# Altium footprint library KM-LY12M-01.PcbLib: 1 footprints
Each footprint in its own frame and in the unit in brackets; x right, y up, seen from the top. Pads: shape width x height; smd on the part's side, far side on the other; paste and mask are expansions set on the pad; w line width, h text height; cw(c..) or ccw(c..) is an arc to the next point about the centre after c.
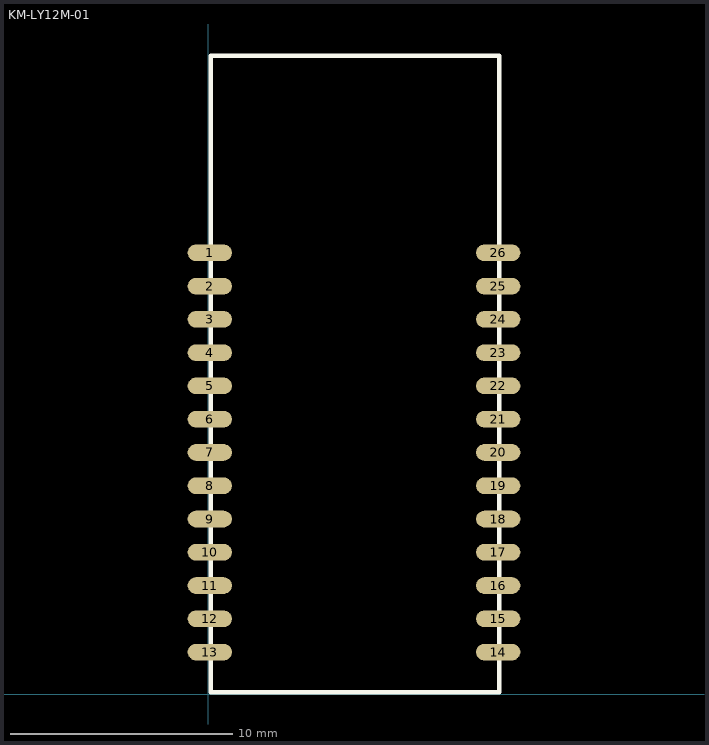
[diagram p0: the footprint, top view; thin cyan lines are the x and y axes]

## KM-LY12M-01 [mm]
pads (26):
  oval 2x0.75 smd: 1(0.077,19.897) 2(0.077,18.397) 3(0.077,16.897) 4(0.077,15.397) 5(0.077,13.897) 6(0.077,12.397) 7(0.077,10.897) 8(0.077,9.397) 9(0.077,7.897) 10(0.077,6.397) 11(0.077,4.897) 12(0.077,3.397) 13(0.077,1.897) 14(13.077,1.897) 15(13.077,3.397) 16(13.077,4.897) 17(13.077,6.397) 18(13.077,7.897) 19(13.077,9.397) 20(13.077,10.897) 21(13.077,12.397) 22(13.077,13.897) 23(13.077,15.397) 24(13.077,16.897) 25(13.077,18.397) 26(13.077,19.897)
Top Overlay:
  lines w0.2: 13.127,28.78 13.127,0.09 0.127,0.09 0.127,28.78 13.133,28.78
